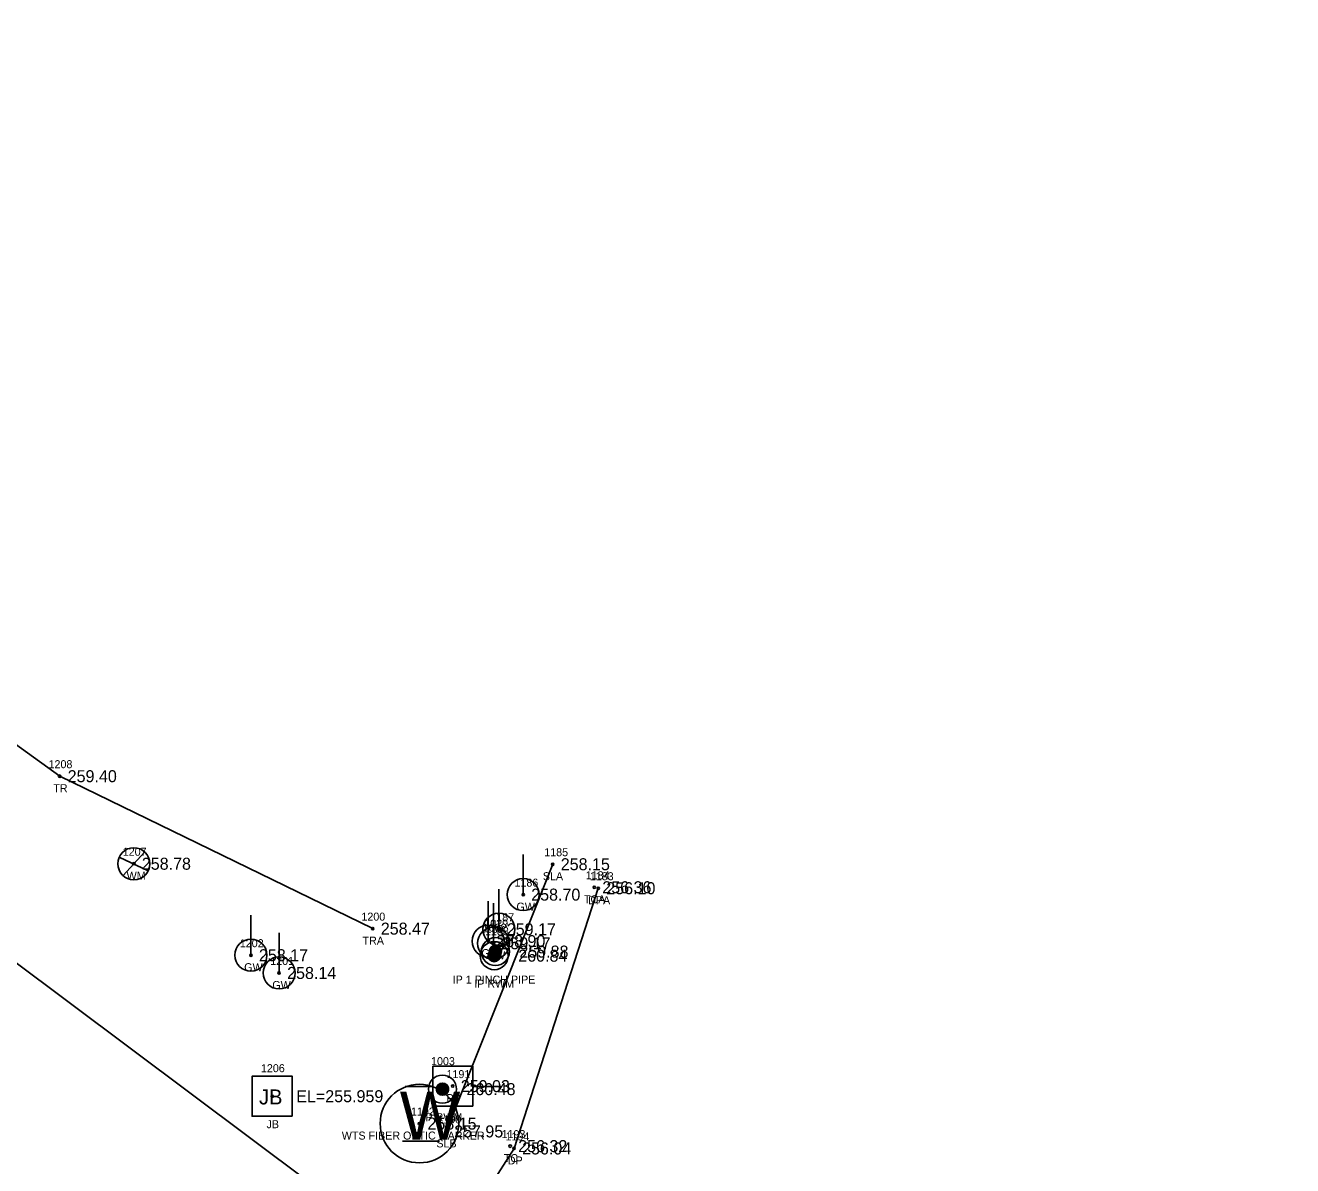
# Model space of a CAD drawing. Extents: x 1961231 to 1962574, y 799865 to 801120.
# Drawn here: x 1961948.3 to 1962106.6, y 800572.1 to 800714.6 of the extents above; entities that cross this region are included whole.
import ezdxf

# ---------------------------------------------------------------- set-up
doc = ezdxf.new("R2010")
doc.units = 0
for name, color, linetype in [('RD_EX_Conc_txCode', 7, 'Continuous'), ('RD_EX_DR_Inlet', 7, 'Continuous'), ('RD_EX_DR_Inlet_txCode', 7, 'Continuous'), ('RD_EX_Driveway', 7, 'Continuous'), ('RD_EX_Driveway_txCode', 7, 'Continuous'), ('RD_EX_DV_Prop_txCode', 7, 'Continuous'), ('RD_EX_DV_PropPin', 7, 'Continuous'), ('RD_EX_Road', 7, 'Continuous'), ('RD_EX_TX_Conc_ELEV', 7, 'Continuous'), ('RD_EX_TX_DR_Inlet_ELEV', 7, 'Continuous'), ('RD_EX_TX_Driveway_ELEV', 7, 'Continuous'), ('RD_EX_TX_DV_Prop_ELEV', 7, 'Continuous'), ('RD_EX_TX_UT_ELEV', 7, 'Continuous'), ('RD_EX_TX_VEG_ELEV', 7, 'Continuous'), ('RD_EX_UT', 7, 'Continuous'), ('RD_EX_UT_txCode', 7, 'Continuous'), ('RD_EX_VEG', 7, 'Continuous'), ('RD_EX_VEG_txCode', 7, 'Continuous'), ('RD_HC_Survey_ELEV', 7, 'Continuous'), ('RD_SMD_Locator', 7, 'Continuous')]:
    doc.layers.add(name, color=color, linetype=linetype)

msp = doc.modelspace()

# ---------------------------------------------------------------- linework, layer by layer
at = {"layer": 'RD_EX_DR_Inlet'}
msp.add_line((1961981.58, 800578.28), (1961981.58, 800583.28), dxfattribs=at)
msp.add_lwpolyline([(1961981.58, 800578.28), (1961981.58, 800583.28), (1961976.58, 800583.28), (1961976.58, 800578.28)], close=True, dxfattribs=at)
at = {"layer": 'RD_EX_Driveway'}
msp.add_lwpolyline([(1962019.82, 800606.78), (1962009.3, 800574.26), (1962006.27, 800569.49), (1962002.82, 800566.18), (1961995.14, 800564.69)], dxfattribs=at)
at = {"layer": 'RD_EX_DV_PropPin'}
for p, q in [((1962006.37, 800598.38), (1962006.37, 800599.33)), ((1962006.4, 800598.34), (1962006.4, 800599.37)), ((1962006.44, 800598.31), (1962006.44, 800599.41)), ((1962006.47, 800598.28), (1962006.47, 800599.44)), ((1962006.51, 800598.25), (1962006.51, 800599.47)), ((1962006.54, 800598.22), (1962006.54, 800599.49)), ((1962006.58, 800598.2), (1962006.58, 800599.51)), ((1962006.61, 800598.18), (1962006.61, 800599.53)), ((1962006.65, 800598.16), (1962006.65, 800599.55)), ((1962006.68, 800598.15), (1962006.68, 800599.56)), ((1962006.72, 800598.14), (1962006.72, 800599.58)), ((1962006.75, 800598.13), (1962006.75, 800599.59)), ((1962006.79, 800598.12), (1962006.79, 800599.6)), ((1962006.82, 800598.11), (1962006.82, 800599.61)), ((1962006.86, 800598.1), (1962006.86, 800599.61)), ((1962006.89, 800598.1), (1962006.89, 800599.61)), ((1962006.93, 800598.1), (1962006.93, 800599.62)), ((1962006.96, 800598.1), (1962006.96, 800599.62)), ((1962007, 800598.1), (1962007, 800599.62)), ((1962007.03, 800598.1), (1962007.03, 800599.61)), ((1962007.07, 800598.1), (1962007.07, 800599.61)), ((1962007.1, 800598.11), (1962007.1, 800599.61)), ((1962007.14, 800598.12), (1962007.14, 800599.6)), ((1962007.17, 800598.13), (1962007.17, 800599.59)), ((1962007.21, 800598.14), (1962007.21, 800599.58)), ((1962007.24, 800598.15), (1962007.24, 800599.56)), ((1962007.28, 800598.16), (1962007.28, 800599.55)), ((1962007.31, 800598.18), (1962007.31, 800599.53)), ((1962007.35, 800598.2), (1962007.35, 800599.51)), ((1962007.38, 800598.22), (1962007.38, 800599.49)), ((1962007.42, 800598.25), (1962007.42, 800599.47)), ((1962007.45, 800598.28), (1962007.45, 800599.44)), ((1962007.49, 800598.31), (1962007.49, 800599.41)), ((1962007.52, 800598.34), (1962007.52, 800599.37)), ((1962007.56, 800598.38), (1962007.56, 800599.33)), ((1962006.08, 800598.15), (1962006.08, 800598.54)), ((1962006.12, 800598.05), (1962006.12, 800598.65)), ((1962006.15, 800597.98), (1962006.15, 800598.72)), ((1962006.19, 800597.92), (1962006.19, 800598.77)), ((1962006.22, 800597.87), (1962006.22, 800598.82)), ((1962006.23, 800598.66), (1962006.23, 800599.05)), ((1962006.26, 800598.56), (1962006.26, 800599.16)), ((1962006.26, 800597.83), (1962006.26, 800598.86)), ((1962006.29, 800597.8), (1962006.29, 800598.9)), ((1962006.3, 800598.49), (1962006.3, 800599.23)), ((1962006.33, 800598.43), (1962006.33, 800599.28)), ((1962006.33, 800597.77), (1962006.33, 800598.93)), ((1962006.36, 800597.74), (1962006.36, 800598.96)), ((1962006.4, 800597.71), (1962006.4, 800598.98)), ((1962006.43, 800597.69), (1962006.43, 800599)), ((1962006.47, 800597.67), (1962006.47, 800599.02)), ((1962006.5, 800597.65), (1962006.5, 800599.04)), ((1962006.54, 800597.64), (1962006.54, 800599.06)), ((1962006.57, 800597.63), (1962006.57, 800599.07)), ((1962006.61, 800597.62), (1962006.61, 800599.08)), ((1962006.64, 800597.61), (1962006.64, 800599.09)), ((1962006.68, 800597.6), (1962006.68, 800599.1)), ((1962006.71, 800597.59), (1962006.71, 800599.1)), ((1962006.75, 800597.59), (1962006.75, 800599.11)), ((1962006.78, 800597.59), (1962006.78, 800599.11)), ((1962006.82, 800597.59), (1962006.82, 800599.11)), ((1962006.85, 800597.59), (1962006.85, 800599.11)), ((1962006.89, 800597.59), (1962006.89, 800599.11)), ((1962006.92, 800597.59), (1962006.92, 800599.1)), ((1962006.96, 800597.6), (1962006.96, 800599.1)), ((1962006.99, 800597.61), (1962006.99, 800599.09)), ((1962007.03, 800597.62), (1962007.03, 800599.08)), ((1962007.06, 800597.63), (1962007.06, 800599.07)), ((1962007.1, 800597.64), (1962007.1, 800599.06)), ((1962007.13, 800597.65), (1962007.13, 800599.04)), ((1962007.17, 800597.67), (1962007.17, 800599.02)), ((1962007.2, 800597.69), (1962007.2, 800599)), ((1962007.24, 800597.71), (1962007.24, 800598.98)), ((1962007.27, 800597.74), (1962007.27, 800598.96)), ((1962007.31, 800597.77), (1962007.31, 800598.93)), ((1962007.34, 800597.8), (1962007.34, 800598.9)), ((1962007.38, 800597.83), (1962007.38, 800598.86)), ((1962007.41, 800597.87), (1962007.41, 800598.82)), ((1962007.45, 800597.92), (1962007.45, 800598.77)), ((1962007.48, 800597.98), (1962007.48, 800598.72)), ((1962007.52, 800598.05), (1962007.52, 800598.65)), ((1962007.55, 800598.15), (1962007.55, 800598.54)), ((1962007.59, 800598.43), (1962007.59, 800599.28)), ((1962007.63, 800598.49), (1962007.63, 800599.23)), ((1962007.66, 800598.56), (1962007.66, 800599.16)), ((1962007.7, 800598.66), (1962007.7, 800599.05)), ((1961999.65, 800581.37), (1961999.65, 800581.96)), ((1961999.69, 800581.3), (1961999.69, 800582.03)), ((1961999.72, 800581.24), (1961999.72, 800582.09)), ((1961999.76, 800581.19), (1961999.76, 800582.14)), ((1961999.79, 800581.15), (1961999.79, 800582.18)), ((1961999.83, 800581.11), (1961999.83, 800582.22)), ((1961999.86, 800581.08), (1961999.86, 800582.25)), ((1961999.9, 800581.06), (1961999.9, 800582.27)), ((1961999.93, 800581.03), (1961999.93, 800582.3)), ((1961999.97, 800581.01), (1961999.97, 800582.32)), ((1962000, 800580.99), (1962000, 800582.34)), ((1962000.04, 800580.97), (1962000.04, 800582.36)), ((1962000.07, 800580.96), (1962000.07, 800582.37)), ((1962000.11, 800580.94), (1962000.11, 800582.39)), ((1962000.14, 800580.93), (1962000.14, 800582.4)), ((1962000.18, 800580.92), (1962000.18, 800582.41)), ((1962000.21, 800580.92), (1962000.21, 800582.41)), ((1962000.25, 800580.91), (1962000.25, 800582.42)), ((1962000.28, 800580.91), (1962000.28, 800582.42)), ((1962000.32, 800580.9), (1962000.32, 800582.43)), ((1962000.35, 800580.9), (1962000.35, 800582.43)), ((1962000.39, 800580.9), (1962000.39, 800582.43)), ((1962000.42, 800580.91), (1962000.42, 800582.42)), ((1962000.46, 800580.91), (1962000.46, 800582.42)), ((1962000.49, 800580.92), (1962000.49, 800582.41)), ((1962000.53, 800580.92), (1962000.53, 800582.41)), ((1962000.56, 800580.93), (1962000.56, 800582.4)), ((1962000.6, 800580.94), (1962000.6, 800582.39)), ((1962000.63, 800580.96), (1962000.63, 800582.37)), ((1962000.67, 800580.97), (1962000.67, 800582.36)), ((1962000.7, 800580.99), (1962000.7, 800582.34)), ((1962000.74, 800581.01), (1962000.74, 800582.32)), ((1962000.77, 800581.03), (1962000.77, 800582.3)), ((1962000.81, 800581.06), (1962000.81, 800582.27)), ((1962000.84, 800581.08), (1962000.84, 800582.25)), ((1962000.88, 800581.11), (1962000.88, 800582.22)), ((1962000.91, 800581.15), (1962000.91, 800582.18)), ((1962000.95, 800581.19), (1962000.95, 800582.14)), ((1962000.98, 800581.24), (1962000.98, 800582.09)), ((1962001.02, 800581.3), (1962001.02, 800582.03)), ((1962001.05, 800581.37), (1962001.05, 800581.96)), ((1961999.62, 800581.47), (1961999.62, 800581.86)), ((1962001.09, 800581.47), (1962001.09, 800581.86))]:
    msp.add_line(p, q, dxfattribs=at)
for centre, radius in [((1962006.82, 800598.35), 1.75), ((1962006.96, 800598.86), 1.75), ((1962006.96, 800598.86), 0.761), ((1962006.82, 800598.35), 0.761), ((1962000.35, 800581.67), 1.75), ((1962000.35, 800581.67), 0.761)]:
    msp.add_circle(centre, radius, dxfattribs=at)
at = {"layer": 'RD_EX_Road'}
msp.add_lwpolyline([(1962276.74, 800366.53), (1962275.76, 800367.28), (1962226.46, 800400.66), (1962183.05, 800429.73), (1962145.98, 800455.38), (1962104.4, 800484.06), (1962056.77, 800517.94), (1962023.95, 800541.05), (1961991.87, 800563.56), (1961983.89, 800569.94), (1961938.77, 800603.67), (1961913.43, 800623.83), (1961897.73, 800636.17), (1961851.62, 800671.61), (1961815.86, 800699.48), (1961795.77, 800715.49), (1961771.88, 800733.73), (1961750.77, 800750.96), (1961735.63, 800762.82), (1961702.92, 800788.52)], dxfattribs=at)
at = {"layer": 'RD_EX_UT'}
for p, q in [((1961959.97, 800610.68), (1961963.6, 800608.96)), ((1961960.45, 800608.38), (1961963.12, 800611.28)), ((1962010.44, 800605.98), (1962010.44, 800610.98)), ((1962007.39, 800601.65), (1962007.39, 800606.65)), ((1962006.07, 800600.17), (1962006.07, 800605.17)), ((1962006.73, 800599.9), (1962006.73, 800604.9)), ((1961976.43, 800598.41), (1961976.43, 800603.41)), ((1961979.95, 800596.19), (1961979.95, 800601.19)), ((1962004.14, 800584.56), (1961999.14, 800584.56)), ((1961999.14, 800584.56), (1961999.14, 800579.56)), ((1962004.14, 800579.56), (1962004.14, 800584.56)), ((1961995.7, 800582), (1961999.17, 800582)), ((1962004.06, 800582), (1962007.7, 800582)), ((1961999.14, 800579.56), (1962004.14, 800579.56)), ((1961995.36, 800575.16), (1961999.98, 800575.16))]:
    msp.add_line(p, q, dxfattribs=at)
for centre, radius in [((1961961.8, 800609.84), 2), ((1962010.44, 800605.98), 2), ((1962007.39, 800601.65), 2), ((1962006.07, 800600.17), 2), ((1962006.73, 800599.9), 2), ((1961976.43, 800598.41), 2), ((1961979.95, 800596.19), 2), ((1961997.48, 800577.37), 4.91)]:
    msp.add_circle(centre, radius, dxfattribs=at)
at = {"layer": 'RD_EX_VEG'}
msp.add_line((1962014.13, 800609.78), (1962000.81, 800576.39), dxfattribs=at)
msp.add_lwpolyline([(1961991.65, 800601.73), (1961952.54, 800620.78), (1961908.97, 800652.23), (1961862.96, 800688.46), (1961806.36, 800731.71)], dxfattribs=at)
at = {"layer": 'RD_SMD_Locator'}
for centre in [(1961952.54, 800620.78), (1961961.8, 800609.84), (1962014.13, 800609.78), (1962010.44, 800605.98), (1962019.32, 800606.9), (1962019.82, 800606.78), (1961991.65, 800601.73), (1962007.39, 800601.65), (1962006.07, 800600.17), (1962006.73, 800599.9), (1961976.43, 800598.41), (1962006.82, 800598.35), (1962006.96, 800598.86), (1961979.95, 800596.19), (1962001.64, 800582.05), (1961979.09, 800580.79), (1962000.35, 800581.67), (1961997.48, 800577.37), (1962000.81, 800576.39), (1962008.81, 800574.55), (1962009.3, 800574.26)]:
    msp.add_circle(centre, 0.15, dxfattribs=at)

# ---------------------------------------------------------------- texts
at = {"layer": 'RD_EX_Conc_txCode'}
for s, p in [('1184', (1962018.25, 800607.9)), ('TCA', (1962018.03, 800604.9)), ('1193', (1962007.74, 800575.55)), ('TC', (1962008.01, 800572.55))]:
    msp.add_text(s, height=1, dxfattribs=at).set_placement(p)
at = {"layer": 'RD_EX_DR_Inlet'}
msp.add_text('JB', height=1.875, dxfattribs=at).set_placement((1961977.44, 800579.76))
at = {"layer": 'RD_EX_DR_Inlet_txCode'}
for s, p in [('1206', (1961977.68, 800583.79)), ('JB', (1961978.38, 800576.79))]:
    msp.add_text(s, height=1, dxfattribs=at).set_placement(p)
at = {"layer": 'RD_EX_Driveway_txCode'}
for s, p in [('1183', (1962018.76, 800607.78)), ('DPA', (1962018.55, 800604.78)), ('1194', (1962008.23, 800575.26)), ('DP', (1962008.52, 800572.26))]:
    msp.add_text(s, height=1, dxfattribs=at).set_placement(p)
at = {"layer": 'RD_EX_DV_Prop_txCode'}
for s, p in [('1029', (1962005.58, 800601.86)), ('1002', (1962005.39, 800601.35)), ('IP 1 PINCH PIPE', (1962001.63, 800594.86)), ('IP RWM', (1962004.33, 800594.35)), ('1003', (1961998.93, 800584.67)), ('IP RWM', (1961997.86, 800577.67))]:
    msp.add_text(s, height=1, dxfattribs=at).set_placement(p)
at = {"layer": 'RD_EX_TX_Conc_ELEV'}
for s, p in [('256.36', (1962020.32, 800606.15)), ('256.32', (1962009.81, 800573.8))]:
    msp.add_text(s, height=1.5, dxfattribs=at).set_placement(p)
at = {"layer": 'RD_EX_TX_DR_Inlet_ELEV'}
msp.add_text('EL=255.959', height=1.5, dxfattribs=at).set_placement((1961982.09, 800580.04))
at = {"layer": 'RD_EX_TX_Driveway_ELEV'}
for s, p in [('256.10', (1962020.82, 800606.03)), ('256.04', (1962010.3, 800573.51))]:
    msp.add_text(s, height=1.5, dxfattribs=at).set_placement(p)
at = {"layer": 'RD_EX_TX_DV_Prop_ELEV'}
for s, p in [('259.88', (1962009.96, 800598.11)), ('260.84', (1962009.82, 800597.6)), ('260.48', (1962003.35, 800580.92))]:
    msp.add_text(s, height=1.5, dxfattribs=at).set_placement(p)
at = {"layer": 'RD_EX_TX_UT_ELEV'}
for s, p in [('258.78', (1961962.8, 800609.09)), ('258.70', (1962011.44, 800605.23)), ('258.90', (1962007.07, 800599.42)), ('259.17', (1962008.39, 800600.9)), ('259.17', (1962007.73, 800599.15)), ('258.17', (1961977.43, 800597.66)), ('258.14', (1961980.95, 800595.44)), ('258.15', (1961998.48, 800576.62))]:
    msp.add_text(s, height=1.5, dxfattribs=at).set_placement(p)
at = {"layer": 'RD_EX_TX_VEG_ELEV'}
for s, p in [('259.40', (1961953.54, 800620.03)), ('258.15', (1962015.13, 800609.03)), ('258.47', (1961992.65, 800600.98)), ('257.95', (1962001.81, 800575.64))]:
    msp.add_text(s, height=1.5, dxfattribs=at).set_placement(p)
at = {"layer": 'RD_EX_UT'}
msp.add_text('W', height=6, dxfattribs=at).set_placement((1961995.02, 800575.37))
at = {"layer": 'RD_EX_UT_txCode'}
for s, p in [('1207', (1961960.42, 800610.84)), ('WM', (1961960.9, 800607.84)), ('1186', (1962009.35, 800606.98)), ('GW', (1962009.6, 800603.98)), ('1187', (1962006.33, 800602.65)), ('1189', (1962005.01, 800601.17)), ('1188', (1962005.67, 800600.9)), ('1202', (1961975.04, 800599.41)), ('GW', (1962006.55, 800599.65)), ('1201', (1961978.84, 800597.19)), ('GW', (1962005.23, 800598.17)), ('GW', (1962005.89, 800597.9)), ('GW', (1961975.59, 800596.41)), ('GW', (1961979.1, 800594.19)), ('1191', (1962000.86, 800583.05)), ('PP', (1962000.86, 800580.05)), ('1192', (1961996.42, 800578.37)), ('WTS FIBER OPTIC MARKER', (1961987.78, 800575.37))]:
    msp.add_text(s, height=1, dxfattribs=at).set_placement(p)
at = {"layer": 'RD_EX_VEG_txCode'}
for s, p in [('1208', (1961951.15, 800621.78)), ('TR', (1961951.74, 800618.78)), ('1185', (1962013.07, 800610.78)), ('SLA', (1962012.89, 800607.78)), ('1200', (1961990.23, 800602.73)), ('TRA', (1961990.37, 800599.73)), ('1190', (1961999.71, 800577.39)), ('SLB', (1961999.59, 800574.39))]:
    msp.add_text(s, height=1, dxfattribs=at).set_placement(p)
at = {"layer": 'RD_HC_Survey_ELEV'}
msp.add_text('259.03', height=1.5, dxfattribs=at).set_placement((1962002.64, 800581.3))

doc.saveas('drawing.dxf')
